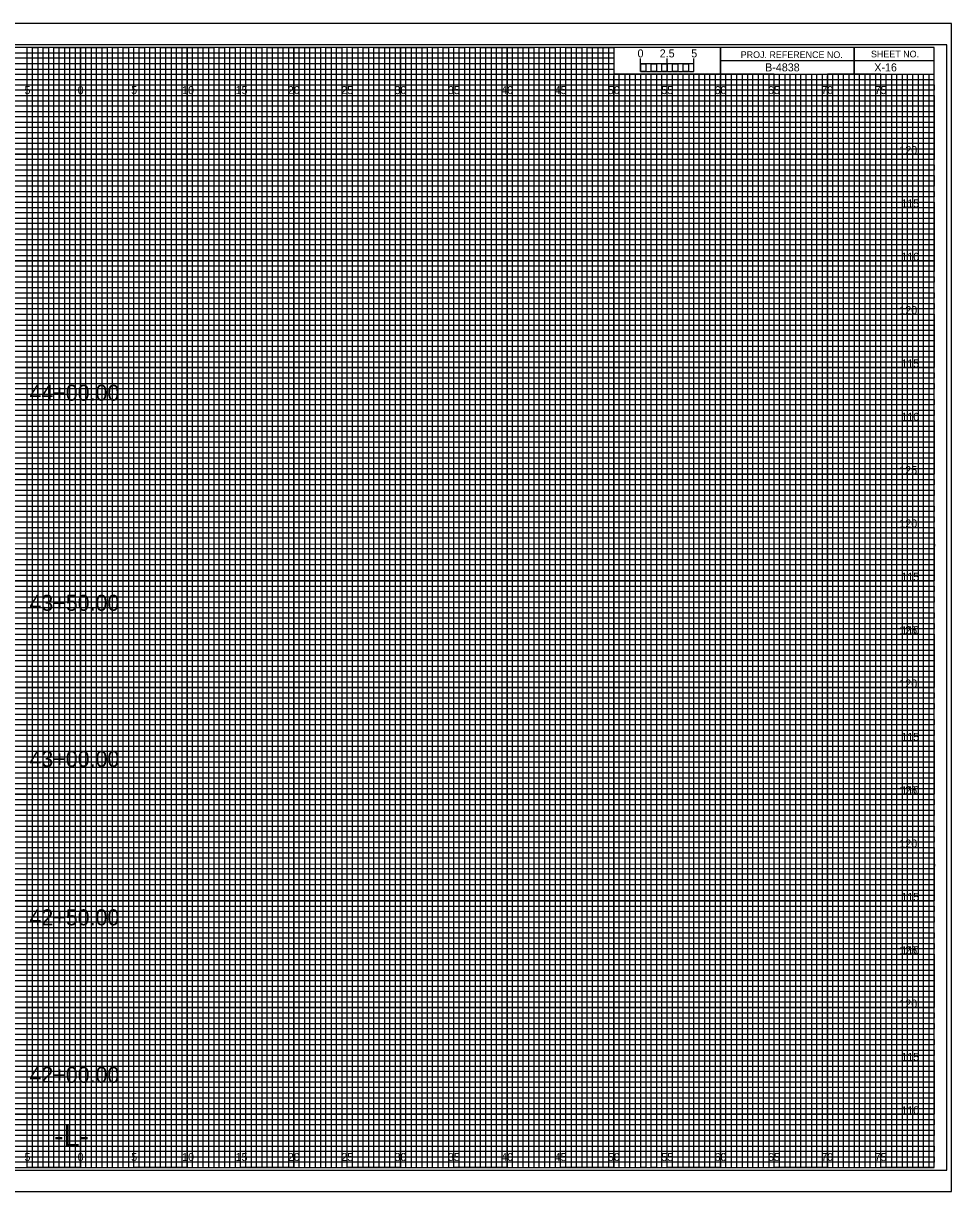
# Model space of a CAD drawing. Extents: x -7 to 182, y -2 to 1647.
# Drawn here: x 74.6 to 161.7, y 1537.8 to 1647.2 of the extents above; entities that cross this region are included whole.
import ezdxf

# ---------------------------------------------------------------- set-up
doc = ezdxf.new("R2010")
doc.units = 0
for name, color, linetype in [('Exist CMT Pavement', 7, 'Continuous'), ('Exist Cross Section Cell', 7, 'Continuous'), ('Exist XS Ground Line', 7, 'Continuous'), ('Prop CMT Pvmt Course 1', 7, 'Continuous'), ('Prop CMT Pvmt Course 2', 7, 'Continuous'), ('Prop CMT Pvmt Course 2 Wedge', 7, 'Continuous'), ('Prop CMT Pvmt Course 3', 7, 'Continuous'), ('Prop CMT Pvmt Surface', 7, 'Continuous'), ('Prop CMT Pvmt Surface Shoulder', 7, 'Continuous'), ('Prop CMT Pvmt Wedge Surface 1', 7, 'Continuous'), ('Prop CMT Pvmt Wedge Surface 2', 7, 'Continuous'), ('Prop CMT Pvmt Wedge Surface 3', 7, 'Continuous'), ('Prop CMT Shld Paved Course 1', 7, 'Continuous'), ('Prop CMT Shld Paved Course 2', 7, 'Continuous'), ('Prop CMT Shld Paved Course 3', 7, 'Continuous'), ('Prop CMT Slope Grass', 7, 'Continuous'), ('Prop CMT Subgrade Earthwork', 7, 'Continuous')]:
    doc.layers.add(name, color=color, linetype=linetype)

msp = doc.modelspace()

# ---------------------------------------------------------------- linework, layer by layer
at = {"layer": 'Exist XS Ground Line'}
for p, q in [((75, 1645), (70, 1645)), ((75, 1540), (75, 1645)), ((85, 1645), (80, 1645)), ((80, 1645), (80, 1540)), ((85, 1540), (85, 1645)), ((95, 1645), (90, 1645)), ((90, 1645), (90, 1540)), ((95, 1540), (95, 1645)), ((105, 1645), (100, 1645)), ((100, 1645), (100, 1540)), ((105, 1540), (105, 1645)), ((115, 1645), (110, 1645)), ((110, 1645), (110, 1540)), ((115, 1540), (115, 1645)), ((125, 1645), (120, 1645)), ((120, 1645), (120, 1540)), ((125, 1540), (125, 1645)), ((130, 1645), (130, 1540)), ((135, 1540), (135, 1642.5)), ((145, 1642.5), (140, 1642.5)), ((140, 1642.5), (140, 1540)), ((145, 1540), (145, 1642.5)), ((155, 1642.5), (150, 1642.5)), ((150, 1642.5), (150, 1540)), ((155, 1540), (155, 1642.5)), ((80, 1540), (75, 1540)), ((90, 1540), (85, 1540)), ((100, 1540), (95, 1540)), ((110, 1540), (105, 1540)), ((120, 1540), (115, 1540)), ((130, 1540), (125, 1540)), ((140, 1540), (135, 1540)), ((150, 1540), (145, 1540)), ((160, 1540), (155, 1540)), ((160, 1540), (160, 1540))]:
    msp.add_line(p, q, dxfattribs=at)
for points in [[(0, 1640), (160, 1640), (160, 1635), (0, 1635)], [(0, 1630), (160, 1630), (160, 1625), (0, 1625)], [(0, 1620), (160, 1620), (160, 1615), (0, 1615)], [(0, 1610), (160, 1610), (160, 1605), (0, 1605)], [(0, 1600), (160, 1600), (160, 1595), (0, 1595)], [(0, 1590), (160, 1590), (160, 1585), (0, 1585)], [(0, 1580), (160, 1580), (160, 1575), (0, 1575)], [(0, 1570), (160, 1570), (160, 1565), (0, 1565)], [(0, 1560), (160, 1560), (160, 1555), (0, 1555)], [(0, 1550), (160, 1550), (160, 1545), (0, 1545)]]:
    msp.add_lwpolyline(points, dxfattribs=at)
at = {"layer": 'Prop CMT Pvmt Course 2'}
for p, q in [((132.5, 1642.75), (132.5, 1643.95)), ((132.5, 1643.45), (132.5, 1643.95)), ((135, 1642.75), (135, 1643.95)), ((137.5, 1642.75), (137.5, 1643.95)), ((137.5, 1643.45), (137.5, 1643.95))]:
    msp.add_line(p, q, dxfattribs=at)
for points in [[(137.5, 1643.45), (132.5, 1643.45), (132.5, 1642.75), (137.5, 1642.75)], [(132.5, 1643.45), (133, 1643.45), (133, 1642.75), (132.5, 1642.75)], [(133.5, 1643.45), (134, 1643.45), (134, 1642.75), (133.5, 1642.75)], [(134.5, 1643.45), (135, 1643.45), (135, 1642.75), (134.5, 1642.75)], [(135.5, 1643.45), (136, 1643.45), (136, 1642.75), (135.5, 1642.75)], [(136.5, 1643.45), (137, 1643.45), (137, 1642.75), (136.5, 1642.75)]]:
    msp.add_lwpolyline(points, close=True, dxfattribs=at)
at = {"layer": 'Prop CMT Pvmt Course 3'}
msp.add_lwpolyline([(-6.7, 1537.75), (161.65, 1537.75), (161.65, 1647.25), (-6.7, 1647.25)], close=True, dxfattribs=at)
at = {"layer": 'Prop CMT Pvmt Wedge Surface 1'}
for p, q in [((0, 1644.5), (130, 1644.5)), ((130, 1643.99), (0, 1643.99)), ((130, 1644.5), (130, 1643.99)), ((0, 1643.5), (130, 1643.5)), ((130, 1642.94), (0, 1642.94)), ((130, 1643.5), (130, 1642.94)), ((0, 1642), (160, 1642))]:
    msp.add_line(p, q, dxfattribs=at)
for points in [[(0, 1641.5), (135, 1641.5), (160, 1641.5), (160, 1641), (0, 1641)], [(0, 1640.5), (160, 1640.5), (160, 1639.5), (0, 1639.5)], [(0, 1639), (160, 1639), (160, 1638.5), (0, 1638.49)], [(0, 1638), (160, 1638), (160, 1637), (0, 1637)], [(0, 1636.5), (160, 1636.5), (160, 1636), (0, 1636)], [(0, 1635.5), (160, 1635.5), (160, 1634.5), (0, 1634.5)], [(0, 1634), (160, 1634), (160, 1633.5), (0, 1633.5)], [(0, 1633), (160, 1633), (160, 1632), (0, 1632)], [(0, 1631.5), (160, 1631.5), (160, 1631), (0, 1631)], [(0, 1630.5), (160, 1630.5), (160, 1629.5), (0, 1629.5)], [(0, 1629), (160, 1629), (160, 1628.5), (0, 1628.5)], [(0, 1628), (160, 1628), (160, 1626.98), (160, 1626.5), (160, 1626), (0, 1626)], [(0, 1627), (160, 1627), (160, 1626.5), (0, 1626.5)], [(0, 1625.5), (160, 1625.5), (160, 1624.5), (0, 1624.52)], [(0, 1624.52), (160, 1624.5), (160, 1624), (0, 1624)], [(0, 1623.5), (160, 1623.5), (160, 1623), (0, 1623)], [(0, 1622), (160, 1622), (160, 1621.5), (0, 1621.5)], [(0, 1621), (160, 1621), (160, 1620.5), (0, 1620.5)], [(-0.04, 1619.44), (160, 1619.44), (160, 1618.94), (-0.04, 1618.94)], [(0, 1618.5), (160, 1618.5), (160, 1618), (0, 1618)], [(0, 1617), (160, 1617), (160, 1616.5), (0, 1616.5)], [(0, 1616), (160, 1616), (160, 1615.5), (0, 1615.5)], [(0, 1614.5), (160, 1614.5), (160, 1614), (0, 1614)], [(0, 1613.5), (160, 1613.5), (160, 1613), (0, 1613)], [(0, 1612), (160, 1612), (160, 1611.5), (0, 1611.5)], [(0, 1611), (160, 1611), (160, 1610.5), (0, 1610.5)], [(0, 1609.5), (160, 1609.5), (160, 1608.99), (0, 1609)], [(0, 1608.5), (160, 1608.5), (160, 1608), (0, 1608)], [(0, 1607), (160, 1607), (160, 1606.5), (0, 1606.5)], [(0, 1606), (160, 1606), (160, 1605.5), (0, 1605.5)], [(0, 1604.5), (160, 1604.5), (160, 1604), (0, 1604)], [(0, 1603.5), (160, 1603.5), (160, 1603), (0, 1603)], [(0, 1602), (160, 1602), (160, 1601.5), (0, 1601.5)], [(0, 1601), (160, 1601), (160, 1600.5), (0, 1600.5)], [(0, 1599.5), (160, 1599.5), (160, 1599), (0, 1599)], [(0, 1598.5), (160.03, 1598.45), (160, 1598), (0, 1598)], [(0, 1597), (160, 1597), (160, 1596.5), (0, 1596.5)], [(0, 1596), (160, 1596), (160, 1595.5), (0, 1595.5)], [(0, 1594.5), (160, 1594.5), (160, 1594), (0, 1594)], [(0, 1593.5), (160, 1593.5), (160, 1593), (0, 1593)], [(0, 1592), (160, 1592), (160, 1591.5), (0, 1591.5)], [(0, 1591), (160, 1591), (160, 1590.5), (0, 1590.5)], [(0, 1589.5), (160, 1589.5), (160, 1589), (0, 1589)], [(0, 1588.5), (160, 1588.5), (160, 1588), (0, 1588)], [(0, 1587), (160, 1587), (160, 1586.5), (0, 1586.5)], [(0, 1586), (160, 1586), (160, 1585.5), (0, 1585.5)], [(0, 1584.5), (160, 1584.5), (160, 1584), (0, 1584)], [(0, 1583.5), (160, 1583.5), (160, 1583), (0, 1583)], [(0, 1582), (160, 1582), (160, 1581.5), (0, 1581.5)], [(0, 1581), (160, 1581), (160, 1580.5), (0, 1580.5)], [(0, 1579.5), (160, 1579.5), (160, 1578.99), (0, 1579)], [(0, 1578.5), (160, 1578.5), (160, 1578), (0, 1578)], [(0, 1577), (160, 1577), (160, 1576.5), (0, 1576.5)], [(0, 1576), (160, 1576), (160, 1575.5), (0, 1575.5)], [(0, 1574.5), (160, 1574.5), (160, 1574), (0, 1574)], [(0, 1573.5), (160, 1573.5), (160, 1573), (0, 1573)], [(0, 1572), (160, 1572), (160, 1571.5), (0, 1571.5)], [(0, 1571), (160, 1571), (160, 1570.5), (0, 1570.5)], [(0, 1569.5), (160, 1569.5), (160, 1569), (0, 1569)], [(0, 1568.5), (160.03, 1568.45), (160, 1568), (0, 1568)], [(0, 1567), (160, 1567), (160, 1566.5), (0, 1566.5)], [(0, 1566), (160, 1566), (160, 1565.5), (0, 1565.5)], [(0, 1564.5), (160, 1564.5), (160, 1564), (0, 1564)], [(0, 1563.5), (160, 1563.5), (160, 1563), (0, 1563)], [(0, 1562), (160, 1562), (160, 1561.5), (0, 1561.5)], [(0, 1561), (160, 1561), (160, 1560.5), (0, 1560.5)], [(0, 1559.5), (160, 1559.5), (160, 1559), (0, 1559)], [(0, 1558.5), (160, 1558.5), (160, 1558), (0, 1558)], [(0, 1557), (160, 1557), (160, 1556.5), (0, 1556.5)], [(0, 1556), (160, 1556), (160, 1555.5), (0, 1555.5)], [(0, 1554.5), (160, 1554.5), (160, 1554), (0, 1554)], [(0, 1553.5), (160, 1553.5), (160, 1553), (0, 1553)], [(0, 1552), (160, 1552), (160, 1551.5), (0, 1551.5)], [(0, 1551), (160, 1551), (160, 1550.5), (0, 1550.5)], [(0, 1549.5), (160, 1549.5), (160, 1549), (0, 1549)], [(0, 1548.5), (160, 1548.5), (160, 1548), (0, 1548)], [(0, 1547), (160, 1547), (160, 1546.5), (0, 1546.5)], [(0, 1546), (160, 1546), (160, 1545.5), (0, 1545.5)], [(0, 1544.5), (160, 1544.5), (160, 1544), (0, 1544)], [(0, 1543.5), (160, 1543.5), (160, 1543), (0, 1543)], [(0, 1542), (160, 1542), (160, 1541.5), (0, 1541.5)], [(0, 1541), (160, 1541), (160, 1540.5), (0, 1540.5)]]:
    msp.add_lwpolyline(points, dxfattribs=at)
at = {"layer": 'Prop CMT Pvmt Wedge Surface 2'}
for p, q in [((152.5, 1645), (152.5, 1642.5)), ((152.5, 1642.5), (152.5, 1645)), ((160, 1643.75), (140, 1643.75)), ((140, 1643.75), (140, 1642.5)), ((140, 1642.5), (160, 1642.5))]:
    msp.add_line(p, q, dxfattribs=at)
for points in [[(160, 1645), (0, 1645), (0, 1540), (160, 1540)], [(140, 1645), (130, 1645), (130, 1642.52), (140, 1642.52)], [(160, 1645), (140, 1645), (140, 1642.5), (160, 1642.5)]]:
    msp.add_lwpolyline(points, close=True, dxfattribs=at)
at = {"layer": 'Prop CMT Pvmt Wedge Surface 3'}
for p, q in [((133.5, 1642.5), (133, 1642.5)), ((133, 1642.5), (133, 1540)), ((133.5, 1540), (133.5, 1642.5)), ((134.5, 1642.5), (134, 1642.5)), ((134, 1642.5), (134, 1540)), ((134.5, 1540), (134.5, 1642.5)), ((133, 1540), (132.5, 1540)), ((134, 1540), (133.5, 1540))]:
    msp.add_line(p, q, dxfattribs=at)
for points in [[(75, 1540), (75.5, 1540), (75.5, 1645), (76, 1645), (76, 1540)], [(76, 1540), (76.5, 1540), (76.5, 1645), (77, 1645), (77, 1540)], [(77.5, 1540), (78, 1540), (78, 1645), (78.5, 1645), (78.5, 1540)], [(78.5, 1540), (79, 1540), (79, 1645), (79.5, 1645), (79.5, 1540)], [(80, 1540), (80.5, 1540), (80.5, 1645), (81, 1645), (81, 1540)], [(81, 1540), (81.5, 1540), (81.5, 1645), (82, 1645), (82, 1540)], [(82.5, 1540), (83, 1540), (83, 1645), (83.5, 1645), (83.5, 1540)], [(83.5, 1540), (84, 1540), (84, 1645), (84.5, 1645), (84.5, 1540)], [(85, 1540), (85.5, 1540), (85.5, 1645), (86, 1645), (86, 1540)], [(86, 1540), (86.5, 1540), (86.5, 1645), (87, 1645), (87, 1540)], [(87.5, 1540), (88, 1540), (88, 1645), (88.5, 1645), (88.5, 1540)], [(88.5, 1540), (89, 1540), (89, 1645), (89.5, 1645), (89.5, 1540)], [(90, 1540), (90.5, 1540), (90.5, 1645), (91, 1645), (91, 1540)], [(91, 1540), (91.5, 1540), (91.5, 1645), (92, 1645), (92, 1540)], [(92.5, 1540), (93, 1540), (93, 1645), (93.5, 1645), (93.5, 1540)], [(93.5, 1540), (94, 1540), (94, 1645), (94.5, 1645), (94.5, 1540)], [(95, 1540), (95.5, 1540), (95.5, 1645), (96, 1645), (96, 1540)], [(96, 1540), (96.5, 1540), (96.5, 1645), (97, 1645), (97, 1540)], [(97.5, 1540), (98, 1540), (98, 1645), (98.5, 1645), (98.5, 1540)], [(98.5, 1540), (99, 1540), (99, 1645), (99.5, 1645), (99.5, 1540)], [(100, 1540), (100.5, 1540), (100.5, 1645), (101, 1645), (101, 1540)], [(101, 1540), (101.5, 1540), (101.5, 1645), (102, 1645), (102, 1540)], [(102.5, 1540), (103, 1540), (103, 1645), (103.5, 1645), (103.5, 1540)], [(103.5, 1540), (104, 1540), (104, 1645), (104.5, 1645), (104.5, 1540)], [(105, 1540), (105.5, 1540), (105.5, 1645), (106, 1645), (106, 1540)], [(106, 1540), (106.5, 1540), (106.5, 1645), (107, 1645), (107, 1540)], [(107.5, 1540), (108, 1540), (108, 1645), (108.5, 1645), (108.5, 1540)], [(108.5, 1540), (109, 1540), (109, 1645), (109.5, 1645), (109.5, 1540)], [(110, 1540), (110.5, 1540), (110.5, 1645), (111, 1645), (111, 1540)], [(111, 1540), (111.5, 1540), (111.5, 1645), (112, 1645), (112, 1540)], [(112.5, 1540), (113, 1540), (113, 1645), (113.5, 1645), (113.5, 1540)], [(113.5, 1540), (114, 1540), (114, 1645), (114.5, 1645), (114.5, 1540)], [(115, 1540), (115.5, 1540), (115.5, 1645), (116, 1645), (116, 1540)], [(116, 1540), (116.5, 1540), (116.5, 1645), (117, 1645), (117, 1540)], [(117.5, 1540), (118, 1540), (118, 1645), (118.5, 1645), (118.5, 1540)], [(118.5, 1540), (119, 1540), (119, 1645), (119.5, 1645), (119.5, 1540)], [(120, 1540), (120.5, 1540), (120.5, 1645), (121, 1645), (121, 1540)], [(121, 1540), (121.5, 1540), (121.5, 1645), (122, 1645), (122, 1540)], [(122.5, 1540), (123, 1540), (123, 1645), (123.5, 1645), (123.5, 1540)], [(123.5, 1540), (124, 1540), (124, 1645), (124.5, 1645), (124.5, 1540)], [(125, 1540), (125.5, 1540), (125.5, 1645), (126, 1645), (126, 1540)], [(126, 1540), (126.5, 1540), (126.5, 1645), (127, 1645), (127, 1540)], [(127.5, 1540), (128, 1540), (128, 1645), (128.5, 1645), (128.5, 1540)], [(128.5, 1540), (129, 1540), (129, 1645), (129.5, 1645), (129.5, 1540)], [(130, 1540), (130.5, 1540), (130.5, 1642.5), (131.01, 1642.5), (131.01, 1540)], [(131, 1540), (131.5, 1540), (131.5, 1642.5), (132, 1642.5), (132, 1540)], [(135, 1540), (135.49, 1540), (135.49, 1642.5), (136, 1642.5), (136, 1540)], [(136, 1540), (136.5, 1540), (136.5, 1642.5), (137.03, 1642.5), (137.03, 1540)], [(137.5, 1540), (138, 1540), (138, 1642.5), (138.5, 1642.5), (138.5, 1540)], [(138.5, 1540), (139, 1540), (139, 1642.5), (139.5, 1642.5), (139.5, 1540)], [(140, 1540), (140.5, 1540), (140.5, 1642.5), (141, 1642.5), (141, 1540)], [(141, 1540), (141.5, 1540), (141.5, 1642.5), (142, 1642.5), (142, 1540)], [(142.5, 1540), (143, 1540), (143, 1642.5), (143.5, 1642.5), (143.5, 1540)], [(143.5, 1540), (144, 1540), (144, 1642.5), (144.5, 1642.5), (144.5, 1540)], [(145, 1540), (145.5, 1540), (145.5, 1642.5), (146, 1642.5), (146, 1540)], [(146, 1540), (146.5, 1540), (146.5, 1642.5), (147, 1642.5), (147, 1540)], [(147.5, 1540), (148, 1540), (148, 1642.5), (148.5, 1642.5), (148.5, 1540)], [(148.5, 1540), (149, 1540), (149, 1642.5), (149.5, 1642.5), (149.5, 1540)], [(150, 1540), (150.5, 1540), (150.5, 1642.5), (151, 1642.5), (151, 1540)], [(151, 1540), (151.5, 1540), (151.5, 1642.5), (152, 1642.5), (152, 1540)], [(152.5, 1540), (153, 1540), (153, 1642.5), (153.5, 1642.5), (153.5, 1540)], [(153.5, 1540), (154, 1540), (154, 1642.5), (154.5, 1642.5), (154.5, 1540)], [(155, 1540), (155.5, 1540), (155.5, 1642.5), (156, 1642.5), (156, 1540)], [(156, 1540), (156.5, 1540), (156.5, 1642.5), (157, 1642.5), (157, 1540)], [(157.5, 1540), (158, 1540), (158, 1642.5), (158.5, 1642.5), (158.5, 1540)], [(158.5, 1540), (159, 1540), (159, 1642.5), (159.5, 1642.5), (159.5, 1540)]]:
    msp.add_lwpolyline(points, dxfattribs=at)
at = {"layer": 'Prop CMT Shld Paved Course 1'}
for p, q in [((75, 1540), (75, 1645)), ((80, 1540), (80, 1645)), ((85, 1540), (85, 1645)), ((90, 1540), (90, 1645)), ((95, 1540), (95, 1645)), ((100, 1540), (100, 1645)), ((105, 1540), (105, 1645)), ((110, 1540), (110, 1645)), ((115, 1540), (115, 1645)), ((120, 1540), (120, 1645)), ((125, 1540), (125, 1645)), ((130, 1540), (130, 1642.34)), ((135, 1540), (135, 1642.34)), ((140, 1540), (140, 1642.34)), ((145, 1540), (145, 1642.34)), ((150, 1540), (150, 1642.34)), ((155, 1540), (155, 1642.34)), ((0, 1640), (160, 1640)), ((0, 1635), (160, 1635)), ((0, 1630), (160, 1630)), ((0, 1625), (160, 1625)), ((0, 1620), (160, 1620)), ((0, 1615), (160, 1615)), ((0, 1610), (160, 1610)), ((0, 1605), (160, 1605)), ((0, 1600), (160, 1600)), ((0, 1595), (160, 1595)), ((0, 1590), (160, 1590)), ((0, 1585), (160, 1585)), ((0, 1580), (160, 1580)), ((0, 1575), (160, 1575)), ((0, 1570), (160, 1570)), ((0, 1565), (160, 1565)), ((0, 1560), (160, 1560)), ((0, 1555), (160, 1555)), ((0, 1550), (160, 1550)), ((0, 1545), (160, 1545))]:
    msp.add_line(p, q, dxfattribs=at)
at = {"layer": 'Prop CMT Shld Paved Course 2'}
for p, q in [((161.65, 1647.25), (-6.7, 1647.25)), ((-6.7, 1537.75), (161.65, 1537.75))]:
    msp.add_line(p, q, dxfattribs=at)
at = {"layer": 'Prop CMT Slope Grass'}
msp.add_lwpolyline([(-5.4, 1539.75), (161.2, 1539.75), (161.2, 1645.25), (-5.4, 1645.25)], close=True, dxfattribs=at)
at = {"layer": 'Prop CMT Subgrade Earthwork'}
for points in [[(72.5, 1540), (77.5, 1540), (77.5, 1645), (82.5, 1645), (82.5, 1540), (87.5, 1540), (87.5, 1645), (92.5, 1645), (92.5, 1540), (97.5, 1540), (97.5, 1645), (102.5, 1645), (102.5, 1540), (107.5, 1540), (107.5, 1645), (112.5, 1645), (112.5, 1540), (117.5, 1540), (117.5, 1645), (122.5, 1645), (122.5, 1540), (127.5, 1540), (127.5, 1645), (129.97, 1645), (130, 1645), (130, 1642.5), (132.5, 1642.5), (132.5, 1540), (137.5, 1540), (137.5, 1642.5), (142.5, 1642.5), (142.5, 1540), (147.5, 1540), (147.5, 1642.5), (152.5, 1642.5), (152.5, 1540), (157.5, 1540), (157.5, 1642.5)], [(0, 1642.5), (137.5, 1642.5)], [(0, 1632.5), (160, 1632.5), (160, 1637.5), (0, 1637.5)], [(0, 1622.5), (160, 1622.5), (160, 1627.5), (0, 1627.5)], [(0, 1612.5), (160, 1612.5), (160, 1617.5), (0, 1617.5)], [(0, 1602.5), (160, 1602.5), (160, 1607.5), (0, 1607.5)], [(0, 1592.5), (160, 1592.5), (160, 1597.5), (0, 1597.5)], [(0, 1582.5), (160, 1582.5), (160, 1587.5), (0, 1587.5)], [(0, 1572.5), (160, 1572.5), (160, 1577.5), (0, 1577.5)], [(0, 1562.5), (160, 1562.5), (160, 1567.5), (0, 1567.5)], [(0, 1552.5), (160, 1552.5), (160, 1557.5), (0, 1557.5)], [(0, 1542.5), (160, 1542.5), (160, 1547.5), (0, 1547.5)]]:
    msp.add_lwpolyline(points, dxfattribs=at)

# ---------------------------------------------------------------- texts
at = {"layer": 'Exist CMT Pavement'}
for s, p in [('44+00.00', (75.21, 1611.88)), ('43+50.00', (75.21, 1592.19)), ('43+00.00', (75.21, 1577.56)), ('42+50.00', (75.21, 1562.71)), ('42+00.00', (75.21, 1547.95))]:
    msp.add_text(s, height=1.5, dxfattribs=at).set_placement(p)
at = {"layer": 'Exist Cross Section Cell'}
for s, p in [('5', (74.74, 1640.62)), ('0', (79.73, 1640.62)), ('0', (79.73, 1640.62)), ('5', (84.74, 1640.62)), ('10', (89.52, 1640.62)), ('15', (94.53, 1640.62)), ('20', (99.43, 1640.62)), ('25', (104.44, 1640.62)), ('30', (109.43, 1640.62)), ('35', (114.44, 1640.62)), ('40', (119.43, 1640.62)), ('45', (124.44, 1640.62)), ('50', (129.43, 1640.62)), ('55', (134.44, 1640.62)), ('60', (139.43, 1640.62)), ('65', (144.44, 1640.62)), ('70', (149.43, 1640.62)), ('75', (154.44, 1640.62)), ('5', (74.74, 1540.62)), ('0', (79.73, 1540.62)), ('0', (79.73, 1540.62)), ('5', (84.74, 1540.62)), ('10', (89.52, 1540.62)), ('15', (94.53, 1540.62)), ('20', (99.43, 1540.62)), ('25', (104.44, 1540.62)), ('30', (109.43, 1540.62)), ('35', (114.44, 1540.62)), ('40', (119.43, 1540.62)), ('45', (124.44, 1540.62)), ('50', (129.43, 1540.62)), ('55', (134.44, 1540.62)), ('60', (139.43, 1540.62)), ('65', (144.44, 1540.62)), ('70', (149.43, 1540.62)), ('75', (154.44, 1540.62))]:
    msp.add_text(s, height=0.75, dxfattribs=at).set_placement(p)
at = {"layer": 'Prop CMT Pvmt Course 1'}
msp.add_text('-L-', height=2, dxfattribs=at).set_placement((77.53, 1542))
at = {"layer": 'Prop CMT Pvmt Course 2'}
msp.add_text('0', height=0.75, dxfattribs=at).set_placement((132.21, 1644.06))
at = {"layer": 'Prop CMT Pvmt Course 2 Wedge'}
for s, p in [('2.5', (134.29, 1644.06)), ('5', (137.24, 1644.06))]:
    msp.add_text(s, height=0.75, dxfattribs=at).set_placement(p)
at = {"layer": 'Prop CMT Pvmt Surface'}
msp.add_text('X-16', height=0.75, dxfattribs=at).set_placement((154.4, 1642.75))
at = {"layer": 'Prop CMT Pvmt Surface Shoulder'}
msp.add_text('B-4838', height=0.75, dxfattribs=at).set_placement((144.17, 1642.75))
at = {"layer": 'Prop CMT Pvmt Wedge Surface 2'}
for s, p in [('SHEET NO.', (154.09, 1644.06)), ('PROJ. REFERENCE NO.', (141.88, 1644))]:
    msp.add_text(s, height=0.625, dxfattribs=at).set_placement(p)
at = {"layer": 'Prop CMT Shld Paved Course 3'}
for s, p in [('120', (156.75, 1635)), ('115', (156.93, 1630)), ('110', (156.94, 1625)), ('120', (156.75, 1620)), ('115', (156.93, 1615)), ('110', (156.94, 1610)), ('125', (156.74, 1605)), ('120', (156.75, 1600)), ('115', (156.93, 1595)), ('125', (156.74, 1590)), ('110', (156.94, 1590)), ('120', (156.75, 1585)), ('115', (156.93, 1580)), ('125', (156.74, 1575)), ('110', (156.94, 1575)), ('120', (156.75, 1570)), ('115', (156.93, 1565)), ('125', (156.74, 1560)), ('110', (156.94, 1560)), ('120', (156.75, 1555)), ('115', (156.93, 1550)), ('110', (156.94, 1545))]:
    msp.add_text(s, height=0.75, dxfattribs=at).set_placement(p)

doc.saveas('drawing.dxf')
